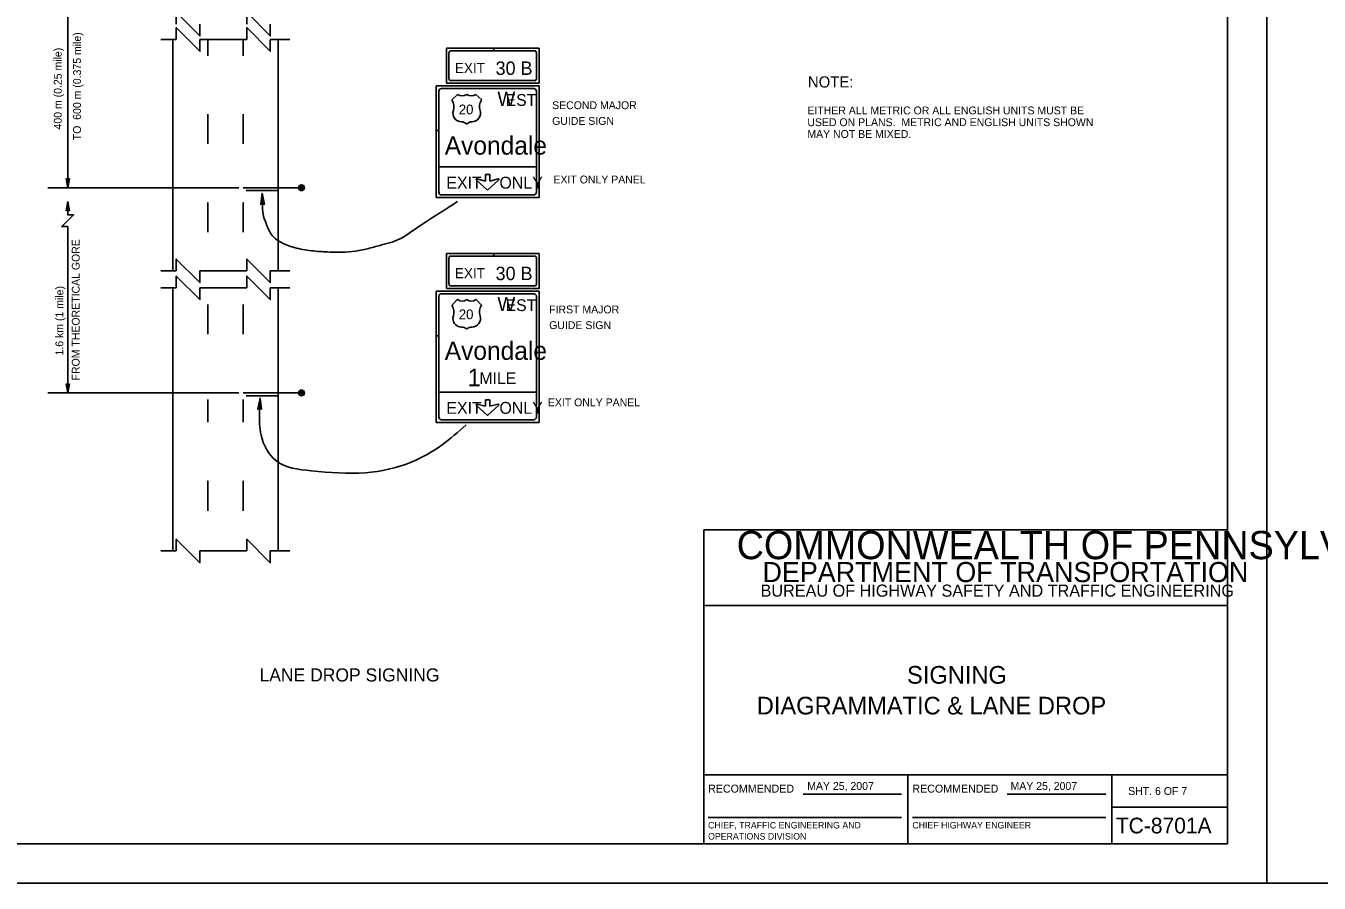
# Model space of a CAD drawing. Extents: x 640994 to 644422, y 298458 to 299646.
# Drawn here: x 642202.5 to 642696.3, y 298457.6 to 298785.1 of the extents above; entities that cross this region are included whole.
import ezdxf

# ---------------------------------------------------------------- set-up
doc = ezdxf.new("R2010")
doc.units = 0
for name, color, linetype in [('1', 7, 'Continuous'), ('2', 7, 'Continuous'), ('XCS-GRID-MIN', 7, 'Continuous')]:
    doc.layers.add(name, color=color, linetype=linetype)

msp = doc.modelspace()

# ---------------------------------------------------------------- linework, layer by layer
at = {"layer": '1'}
for p, q in [((642661.31, 298472.63), (642661.31, 299036.63)), ((642461.31, 298472.63), (642461.31, 298592.63)), ((642461.31, 298592.63), (642661.31, 298592.63)), ((642661.31, 298563.63), (642461.31, 298563.63)), ((642461.31, 298499), (642661.31, 298499)), ((642539.31, 298499), (642539.31, 298472.63)), ((642617.19, 298472.63), (642617.19, 298499)), ((642499.24, 298491.57), (642536.87, 298491.57)), ((642577.24, 298491.57), (642614.87, 298491.57)), ((642617.19, 298486.63), (642661.31, 298486.63)), ((642462.99, 298482.68), (642536.87, 298482.68)), ((642540.99, 298482.68), (642614.87, 298482.68)), ((642661.31, 298472.63), (641875.31, 298472.63)), ((641875.31, 298472.63), (642461.31, 298472.63))]:
    msp.add_line(p, q, dxfattribs=at)
at = {"layer": '2'}
for p, q in [((642218.56, 298821.75), (642218.56, 298723.25)), ((642254.06, 298779.88), (642259.94, 298779.88)), ((642258.56, 298691.5), (642258.56, 298780.13)), ((642268.94, 298779.88), (642286.81, 298779.88)), ((642271.94, 298773.63), (642271.94, 298780.13)), ((642285.44, 298773.63), (642285.44, 298780.13)), ((642295.81, 298779.88), (642303.31, 298779.88)), ((642298.81, 298691.5), (642298.81, 298780.13)), ((642271.94, 298773.63), (642271.94, 298773.63)), ((642285.44, 298773.63), (642285.44, 298773.63)), ((642381.12, 298776.5), (642363.06, 298776.5)), ((642363.06, 298776.5), (642363.06, 298763.13)), ((642364.06, 298764.88), (642364.06, 298774.75)), ((642364.81, 298775.5), (642381.12, 298775.5)), ((642381.12, 298775.5), (642381.12, 298776.5)), ((642398.44, 298776.5), (642381.12, 298776.5)), ((642381.12, 298776.5), (642381.12, 298775.5)), ((642381.12, 298775.5), (642396.81, 298775.5)), ((642397.44, 298774.75), (642397.44, 298764.88)), ((642398.44, 298763.13), (642398.44, 298776.5)), ((642363.06, 298763.13), (642398.44, 298763.13)), ((642396.81, 298764.13), (642364.81, 298764.13)), ((642359.19, 298745.06), (642359.19, 298762.13)), ((642359.19, 298762.13), (642398.44, 298762.13)), ((642360.19, 298760.13), (642360.19, 298745.06)), ((642396.44, 298761.13), (642361.19, 298761.13)), ((642365.19, 298756.75), (642367.31, 298758.88)), ((642374.31, 298758.88), (642376.56, 298756.75)), ((642397.44, 298721.5), (642397.44, 298760.13)), ((642398.44, 298762.13), (642398.44, 298719.5)), ((642271.94, 298751.38), (642271.94, 298751.38)), ((642271.94, 298740), (642271.94, 298751.38)), ((642285.44, 298751.38), (642285.44, 298751.38)), ((642285.44, 298740), (642285.44, 298751.38)), ((642368.81, 298748.38), (642368.81, 298748.38)), ((642370.81, 298753.13), (642370.81, 298753.13)), ((642370.81, 298753.13), (642370.81, 298753.13)), ((642370.81, 298753.13), (642370.81, 298753.13)), ((642370.81, 298753.13), (642370.81, 298753.13)), ((642370.81, 298753.13), (642370.81, 298753.13)), ((642372.94, 298748.38), (642372.94, 298748.38)), ((642373.06, 298751.13), (642373.06, 298751.13)), ((642376.06, 298751.75), (642376.06, 298751.75)), ((642360.19, 298745.06), (642359.19, 298745.06)), ((642359.19, 298719.5), (642359.19, 298745.06)), ((642359.19, 298745.06), (642360.19, 298745.06)), ((642360.19, 298745.06), (642360.19, 298721.5)), ((642271.94, 298740), (642271.94, 298740)), ((642285.44, 298740), (642285.44, 298740)), ((642378.69, 298739.38), (642378.69, 298739.38)), ((642218.56, 298723.25), (642217.94, 298726.75)), ((642217.94, 298726.75), (642218.19, 298726.63)), ((642218.44, 298726.5), (642218.19, 298726.63)), ((642218.19, 298726.63), (642218.56, 298723.25)), ((642218.56, 298723.25), (642218.44, 298726.5)), ((642219.19, 298726.75), (642218.56, 298723.25)), ((642218.56, 298723.25), (642219.06, 298726.63)), ((642218.81, 298726.5), (642218.56, 298723.25)), ((642219.06, 298726.63), (642218.81, 298726.5)), ((642219.06, 298726.63), (642219.19, 298726.75)), ((642306.81, 298723.13), (642307.94, 298724.25)), ((642308.56, 298723.75), (642306.81, 298723.13)), ((642307.94, 298724.25), (642306.94, 298723.75)), ((642307.06, 298722.63), (642307.06, 298723.75)), ((642307.06, 298723.75), (642307.44, 298722.5)), ((642307.44, 298722.5), (642307.56, 298724)), ((642307.56, 298724), (642307.94, 298722.38)), ((642307.69, 298722.38), (642308.56, 298723.75)), ((642307.94, 298722.38), (642307.94, 298724.25)), ((642307.94, 298724.25), (642308.31, 298722.5)), ((642308.31, 298722.5), (642308.31, 298724)), ((642308.31, 298724), (642308.56, 298723.13)), ((642374.44, 298726.25), (642378.81, 298722.25)), ((642377.94, 298725.75), (642374.69, 298726.63)), ((642379.69, 298728.25), (642377.94, 298728.25)), ((642378.81, 298722.25), (642383.06, 298726.25)), ((642382.81, 298726.63), (642379.69, 298725.75)), ((642283.81, 298723.25), (642210.94, 298723.25)), ((642285.44, 298723.25), (642307.81, 298723.25)), ((642286.56, 298722.13), (642298.81, 298722.13)), ((642308.56, 298723.13), (642307.69, 298722.38)), ((642307.81, 298723.25), (642307.81, 298723.25)), ((642398.44, 298719.5), (642359.19, 298719.5)), ((642361.19, 298720.5), (642396.44, 298720.5)), ((642217.94, 298714.42), (642218.57, 298717.92)), ((642218.07, 298714.54), (642217.94, 298714.42)), ((642218.57, 298717.92), (642218.07, 298714.54)), ((642218.07, 298714.54), (642218.32, 298714.67)), ((642218.32, 298714.67), (642218.57, 298717.92)), ((642218.57, 298717.92), (642218.69, 298714.67)), ((642218.94, 298714.54), (642218.57, 298717.92)), ((642218.57, 298717.92), (642219.19, 298714.42)), ((642218.69, 298714.67), (642218.94, 298714.54)), ((642219.19, 298714.42), (642218.94, 298714.54)), ((642271.94, 298717.75), (642271.94, 298717.75)), ((642271.94, 298717.63), (642271.94, 298717.63)), ((642271.94, 298706.25), (642271.94, 298717.63)), ((642285.44, 298717.75), (642285.44, 298717.75)), ((642285.44, 298717.63), (642285.44, 298717.63)), ((642285.44, 298706.25), (642285.44, 298717.63)), ((642218.56, 298708.38), (642218.56, 298644.88)), ((642271.94, 298706.38), (642271.94, 298706.38)), ((642271.94, 298706.25), (642271.94, 298706.25)), ((642285.44, 298706.38), (642285.44, 298706.38)), ((642285.44, 298706.25), (642285.44, 298706.25)), ((642363.06, 298684.75), (642363.06, 298698.13)), ((642363.06, 298698.13), (642381.12, 298698.13)), ((642364.06, 298696.38), (642364.06, 298686.5)), ((642381.12, 298697.13), (642364.81, 298697.13)), ((642381.12, 298698.13), (642381.12, 298697.13)), ((642381.12, 298697.13), (642381.12, 298698.13)), ((642381.12, 298698.13), (642398.44, 298698.13)), ((642396.81, 298697.13), (642381.12, 298697.13)), ((642397.44, 298686.5), (642397.44, 298696.38)), ((642398.44, 298698.13), (642398.44, 298684.75)), ((642254.06, 298691.5), (642259.94, 298691.5)), ((642268.94, 298691.5), (642286.81, 298691.5)), ((642295.81, 298691.5), (642303.31, 298691.5)), ((642254.06, 298685), (642259.94, 298685)), ((642258.56, 298584.25), (642258.56, 298685)), ((642268.94, 298685), (642286.81, 298685)), ((642295.81, 298685), (642303.31, 298685)), ((642298.81, 298584.25), (642298.81, 298685)), ((642398.44, 298684.75), (642363.06, 298684.75)), ((642364.81, 298685.75), (642396.81, 298685.75)), ((642359.19, 298683.75), (642398.44, 298683.75)), ((642396.44, 298682.75), (642361.19, 298682.75)), ((642365.19, 298678.25), (642367.31, 298680.63)), ((642374.31, 298680.63), (642376.56, 298678.25)), ((642397.44, 298635.63), (642397.44, 298681.75)), ((642398.44, 298683.75), (642398.44, 298633.63)), ((642271.94, 298678.63), (642271.94, 298678.63)), ((642271.94, 298667.25), (642271.94, 298678.63)), ((642285.44, 298678.63), (642285.44, 298678.63)), ((642285.44, 298667.25), (642285.44, 298678.63)), ((642370.81, 298674.88), (642370.81, 298674.88)), ((642370.81, 298674.88), (642370.81, 298674.88)), ((642370.81, 298674.88), (642370.81, 298674.88)), ((642370.81, 298674.88), (642370.81, 298674.88)), ((642368.81, 298670), (642368.81, 298670)), ((642372.94, 298670), (642372.94, 298670)), ((642373.06, 298672.63), (642373.06, 298672.63)), ((642376.06, 298673.25), (642376.06, 298673.25)), ((642271.94, 298667.25), (642271.94, 298667.25)), ((642285.44, 298667.25), (642285.44, 298667.25)), ((642360.19, 298666.65), (642359.19, 298666.65)), ((642359.19, 298666.65), (642360.19, 298666.65)), ((642283.81, 298644.88), (642210.94, 298644.88)), ((642218.56, 298644.88), (642217.94, 298648.38)), ((642217.94, 298648.38), (642218.19, 298648.25)), ((642218.44, 298648.13), (642218.19, 298648.25)), ((642218.19, 298648.25), (642218.56, 298644.88)), ((642218.56, 298644.88), (642218.44, 298648.13)), ((642219.19, 298648.38), (642218.56, 298644.88)), ((642218.56, 298644.88), (642219.06, 298648.25)), ((642218.81, 298648.13), (642218.56, 298644.88)), ((642219.06, 298648.25), (642218.81, 298648.13)), ((642219.06, 298648.25), (642219.19, 298648.38)), ((642271.94, 298645), (642271.94, 298645)), ((642285.44, 298645), (642285.44, 298645)), ((642285.44, 298644.88), (642307.81, 298644.88)), ((642306.81, 298644.63), (642307.94, 298645.75)), ((642308.56, 298645.38), (642306.81, 298644.63)), ((642307.94, 298645.75), (642306.94, 298645.5)), ((642307.06, 298644.25), (642307.06, 298645.25)), ((642307.06, 298645.25), (642307.44, 298644)), ((642307.44, 298644), (642307.56, 298645.63)), ((642307.56, 298645.63), (642307.94, 298643.88)), ((642307.69, 298643.88), (642308.56, 298645.38)), ((642308.56, 298644.75), (642307.69, 298643.88)), ((642307.81, 298644.88), (642307.81, 298644.88)), ((642307.94, 298643.88), (642307.94, 298645.75)), ((642307.94, 298645.75), (642308.31, 298644.13)), ((642308.31, 298644.13), (642308.31, 298645.63)), ((642308.31, 298645.63), (642308.56, 298644.75)), ((642360.19, 298645.13), (642397.44, 298645.13)), ((642271.94, 298633.75), (642271.94, 298642.38)), ((642285.44, 298633.75), (642285.44, 298642.38)), ((642286.56, 298643.75), (642298.81, 298643.75)), ((642374.44, 298640.25), (642378.81, 298636.25)), ((642377.94, 298639.75), (642374.69, 298640.63)), ((642379.69, 298642.25), (642377.94, 298642.25)), ((642378.81, 298636.25), (642383.06, 298640.25)), ((642382.81, 298640.63), (642379.69, 298639.75)), ((642271.94, 298633.75), (642271.94, 298633.75)), ((642285.44, 298633.75), (642285.44, 298633.75)), ((642398.44, 298633.63), (642359.19, 298633.63)), ((642361.19, 298634.63), (642396.44, 298634.63)), ((642271.94, 298611.38), (642271.94, 298611.38)), ((642271.94, 298611.25), (642271.94, 298611.25)), ((642271.94, 298599.88), (642271.94, 298611.25)), ((642285.44, 298611.38), (642285.44, 298611.38)), ((642285.44, 298611.25), (642285.44, 298611.25)), ((642285.44, 298599.88), (642285.44, 298611.25)), ((642271.94, 298600), (642271.94, 298600)), ((642271.94, 298599.88), (642271.94, 298599.88)), ((642285.44, 298600), (642285.44, 298600)), ((642285.44, 298599.88), (642285.44, 298599.88)), ((642254.06, 298584.5), (642259.94, 298584.5)), ((642258.56, 298584.25), (642258.56, 298584.25)), ((642268.94, 298584.5), (642286.81, 298584.5)), ((642295.81, 298584.5), (642303.31, 298584.5))]:
    msp.add_line(p, q, dxfattribs=at)
for points in [[(642259.94, 298785.75), (642259.94, 298790.25), (642268.94, 298781.25), (642268.94, 298785.75)], [(642286.81, 298785.75), (642286.81, 298790.25), (642295.81, 298781.25), (642295.81, 298785.75)], [(642259.94, 298779.88), (642259.94, 298784.38), (642268.94, 298775.38), (642268.94, 298779.88)], [(642286.81, 298779.88), (642286.81, 298784.38), (642295.81, 298775.38), (642295.81, 298779.88)], [(642360.19, 298731.25), (642397.44, 298731.25)], [(642377.94, 298728.25), (642377.94, 298725.75)], [(642379.69, 298725.75), (642379.69, 298728.25)], [(642292.31, 298717), (642292.56, 298717.13), (642292.69, 298721.13), (642292.31, 298717), (642292.19, 298716.88), (642292.69, 298721.13), (642292.94, 298717.13), (642293.31, 298717), (642292.69, 298721.13), (642293.56, 298716.88), (642293.31, 298717)], [(642218.57, 298708.38), (642216.19, 298708.38), (642220.69, 298712.88), (642218.57, 298712.88), (642218.57, 298717.92)], [(642259.94, 298691.5), (642259.94, 298696), (642268.94, 298687), (642268.94, 298691.5)], [(642286.81, 298691.5), (642286.81, 298696), (642295.81, 298687), (642295.81, 298691.5)], [(642259.94, 298685), (642259.94, 298689.5), (642268.94, 298680.5), (642268.94, 298685)], [(642286.81, 298685), (642286.81, 298689.5), (642295.81, 298680.5), (642295.81, 298685)], [(642359.19, 298666.65), (642359.19, 298683.75)], [(642360.19, 298681.75), (642360.19, 298666.65)], [(642359.19, 298633.63), (642359.19, 298666.65)], [(642360.19, 298666.65), (642360.19, 298635.63)], [(642291.19, 298638.75), (642291.56, 298638.88), (642291.94, 298642.88), (642291.19, 298638.75), (642291.06, 298638.63), (642291.94, 298642.88), (642291.94, 298638.88), (642292.31, 298638.75), (642291.94, 298642.88), (642292.44, 298638.63), (642292.31, 298638.75)], [(642377.94, 298642.25), (642377.94, 298639.75)], [(642379.69, 298639.75), (642379.69, 298642.25)], [(642259.94, 298584.5), (642259.94, 298589), (642268.94, 298580), (642268.94, 298584.5)], [(642286.81, 298584.5), (642286.81, 298589), (642295.81, 298580), (642295.81, 298584.5)]]:
    msp.add_lwpolyline(points, dxfattribs=at)
for centre in [(642307.75, 298723.24), (642307.75, 298644.86)]:
    msp.add_circle(centre, 1.12, dxfattribs=at)
for centre, radius, start, end in [((642361.19, 298760.13), 1, 90, 180), ((642369.08, 298761.24), 2.93, 233.136, 306.864), ((642372.59, 298761.24), 2.93, 233.136, 306.864), ((642396.44, 298760.13), 1, 0, 90), ((642361.41, 298754.14), 4.55, 341.8289, 34.5747), ((642380.25, 298754.14), 4.55, 145.4253, 198.1711), ((642368.83, 298751.69), 3.26, 161.452, 269.9953), ((642368.82, 298745.67), 2.76, 43.7275, 90), ((642372.84, 298745.67), 2.76, 90, 136.2725), ((642372.84, 298751.69), 3.26, 270.0047, 18.548), ((642374.66, 298726.4), 0.217, 75.9638, 226.9667), ((642382.88, 298726.4), 0.217, 313.0251, 104.0537), ((642361.19, 298721.5), 1, 180, 270), ((642396.44, 298721.5), 1, 270, 0), ((642361.19, 298681.75), 1, 90, 180), ((642369.08, 298682.86), 2.93, 233.136, 306.864), ((642372.59, 298682.86), 2.93, 233.136, 306.864), ((642396.44, 298681.75), 1, 0, 90), ((642361.41, 298675.76), 4.55, 341.8289, 34.5747), ((642368.83, 298673.3), 3.26, 161.452, 269.9953), ((642372.84, 298673.3), 3.26, 270.0047, 18.548), ((642380.25, 298675.76), 4.55, 145.4253, 198.1711), ((642368.82, 298667.28), 2.76, 43.7275, 90), ((642372.84, 298667.28), 2.76, 90, 136.2725), ((642374.66, 298640.4), 0.217, 75.9638, 226.9667), ((642382.88, 298640.4), 0.217, 313.0251, 104.0537), ((642361.19, 298635.63), 1, 180, 270), ((642396.44, 298635.63), 1, 270, 0)]:
    msp.add_arc(centre, radius, start, end, dxfattribs=at)
for centre, major_axis, start_param, end_param in [((642364.77, 298774.74), (0, -0.792), 3.141593, 4.712389), ((642396.8, 298774.74), (0, 0.792), 4.712389, 6.283185), ((642364.77, 298764.89), (0, -0.792), 4.712389, 6.283185), ((642396.8, 298764.89), (0, 0.792), 3.141593, 4.712389), ((642364.77, 298696.36), (0, -0.792), 3.141593, 4.712389), ((642396.8, 298696.36), (0, 0.792), 4.712389, 6.283185), ((642364.77, 298686.51), (0, -0.792), 4.712389, 6.283185), ((642396.8, 298686.51), (0, 0.792), 3.141593, 4.712389)]:
    msp.add_ellipse(centre, major_axis=major_axis, ratio=0.827467, start_param=start_param, end_param=end_param, dxfattribs=at)
for points in [[(642292.69, 298721.13), (642292.81, 298717), (642293.06, 298713.13), (642294.19, 298709.75), (642296.56, 298705), (642299.31, 298702.75), (642304.19, 298700.63), (642310.81, 298699.25), (642316.94, 298698.75), (642323.19, 298698.63), (642328.31, 298699), (642333.69, 298700.13), (642338.31, 298701.38), (642342.31, 298702.5), (642345.94, 298704), (642348.31, 298705.5), (642355.81, 298710.63), (642362.19, 298714.63), (642367.31, 298718)], [(642291.94, 298642.88), (642291.69, 298637.13), (642292.31, 298628.75), (642297.94, 298619), (642311.44, 298615.13), (642332.19, 298614.38), (642349.56, 298618.38), (642361.44, 298625), (642370.56, 298632.63)]]:
    msp.add_spline(points, degree=3, dxfattribs=at)
at = {"layer": 'XCS-GRID-MIN'}
for points in [[(641835.31, 299051.63), (642676.31, 299051.63), (642676.31, 298457.63), (641835.31, 298457.63)], [(642676.31, 299051.63), (643517.31, 299051.63), (643517.31, 298457.63), (642676.31, 298457.63)]]:
    msp.add_lwpolyline(points, close=True, dxfattribs=at)

# ---------------------------------------------------------------- texts
at = {"layer": '1'}
for s, height, p in [('COMMONWEALTH OF PENNSYLVANIA', 10.7828, (642473.9, 298581.36)), ('DEPARTMENT OF TRANSPORTATION', 7.6837, (642483.76, 298572.61)), ('BUREAU OF HIGHWAY SAFETY AND TRAFFIC ENGINEERING', 4.6253, (642483.04, 298567.04)), ('SIGNING', 6.75, (642538.96, 298533.81)), ('DIAGRAMMATIC & LANE DROP', 6.75, (642481.59, 298522.06)), ('RECOMMENDED', 3.048, (642462.99, 298492.2)), ('RECOMMENDED', 3.048, (642540.99, 298492.2)), ('SHT. 6 OF 7', 3, (642623.4, 298491.31)), ('TC-8701A', 6, (642618.68, 298476.63)), ('OPERATIONS DIVISION', 2.5, (642462.99, 298474.26)), ('CHIEF, TRAFFIC ENGINEERING AND', 2.5, (642462.99, 298478.51)), ('CHIEF HIGHWAY ENGINEER', 2.5, (642540.99, 298478.51))]:
    msp.add_text(s, height=height, dxfattribs=at).set_placement(p)
at = {"layer": '2'}
for s, rotation, p in [('TO  600 m (0.375 mile)', 90, (642223.54, 298741.38)), ('  400 m (0.25 mile) ', 90, (642216.18, 298743.26)), ('FROM THEORETICAL GORE', 90, (642223.04, 298649.64)), ('1.6 km (1 mile) ', 90, (642216.8, 298659.16)), ('MAY 25, 2007', 360, (642578.47, 298493.24))]:
    msp.add_text(s, height=3, rotation=rotation, dxfattribs=at).set_placement(p)
for s, height, p in [('EXIT', 3.875, (642366.3, 298767.04)), ('30 B', 5.125, (642381.86, 298766.33)), ('NOTE:', 4.25, (642501.12, 298761.53)), ('W', 5.38, (642382.56, 298754.5)), ('EST', 4.5, (642385.69, 298754.5)), ('20', 3.75, (642367.81, 298751.25)), ('SECOND MAJOR', 3, (642403.44, 298753.25)), ('EITHER ALL METRIC OR ALL ENGLISH UNITS MUST BE', 3, (642500.9, 298751.26)), ('GUIDE SIGN', 3, (642403.44, 298747.25)), ('USED ON PLANS.  METRIC AND ENGLISH UNITS SHOWN', 3, (642500.9, 298746.76)), ('MAY NOT BE MIXED.', 3, (642500.9, 298742.26)), ('Avondale', 7, (642362.44, 298735.88)), ('EXIT    ONLY', 4.5457, (642363.06, 298722.88)), ('EXIT ONLY PANEL', 3, (642403.94, 298724.88)), ('EXIT', 3.875, (642366.3, 298688.67)), ('30 B', 5.125, (642381.86, 298687.95)), ('W', 5.38, (642382.56, 298676.13)), ('EST', 4.5, (642385.69, 298676.13)), ('20', 3.75, (642367.81, 298673)), ('FIRST MAJOR', 3, (642402.31, 298675.25)), ('GUIDE SIGN', 3, (642402.31, 298669.25)), ('Avondale', 7, (642362.44, 298657.5)), ('1', 6.75, (642371.19, 298647.38)), ('MILE', 4.5, (642375.69, 298648.25)), ('EXIT    ONLY', 4.5457, (642363.06, 298636.88)), ('EXIT ONLY PANEL', 3, (642401.81, 298639.75)), ('LANE DROP SIGNING', 5, (642291.71, 298534.65)), ('MAY 25, 2007', 3, (642500.85, 298493.24))]:
    msp.add_text(s, height=height, dxfattribs=at).set_placement(p)

doc.saveas('drawing.dxf')
